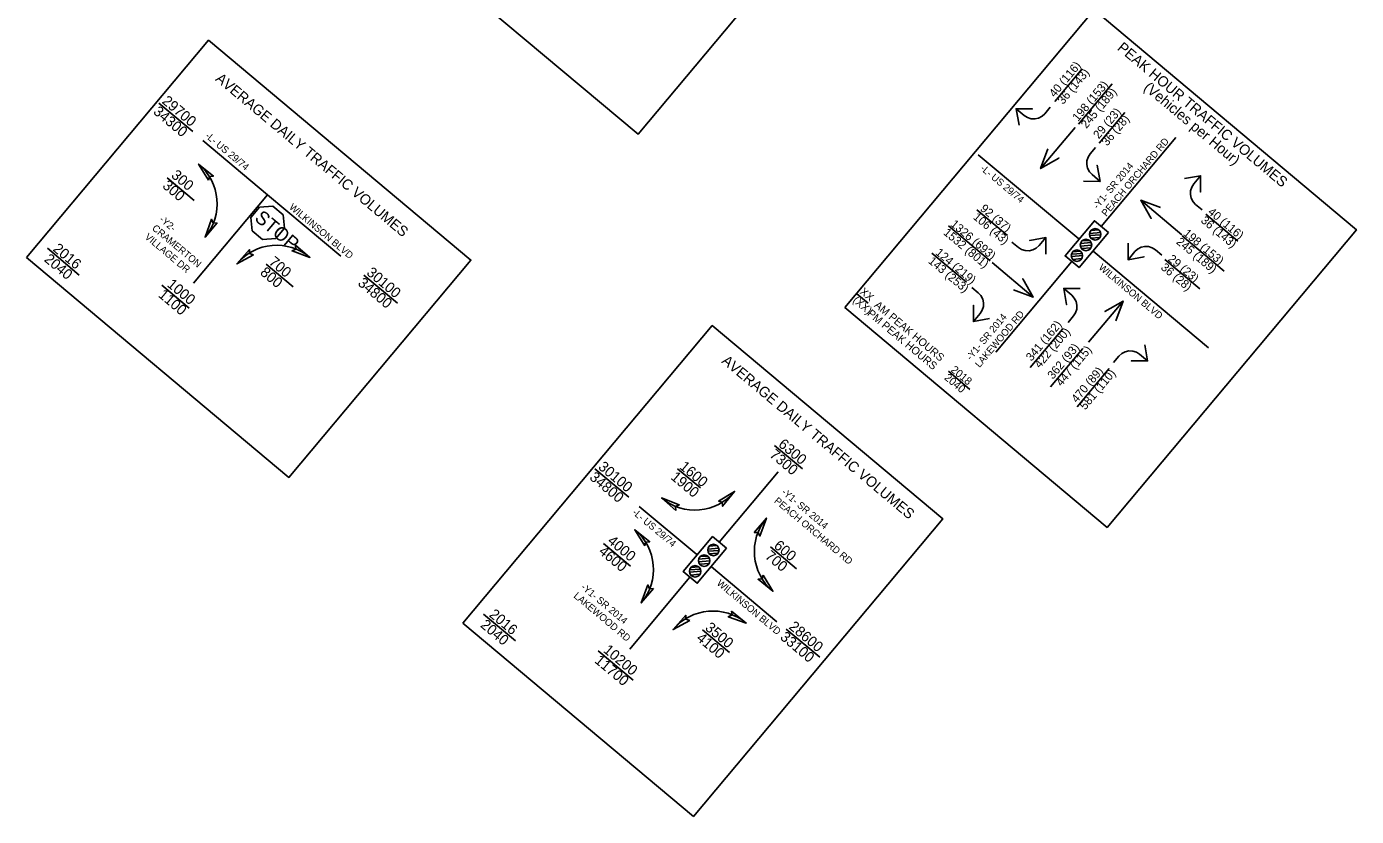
# Model space of a CAD drawing. Extents: x 1257249 to 1258387, y 800228 to 800957.
# Drawn here: x 1257747 to 1258387, y 800228 to 800608 of the extents above; entities that cross this region are included whole.
import ezdxf

# ---------------------------------------------------------------- set-up
doc = ezdxf.new("R2010")
doc.units = 0
for name, color, linetype in [('Exist PHM Traffic Signal CELL', 7, 'Continuous'), ('Pattern 1', 7, 'Continuous'), ('Prop DSN Text', 7, 'Continuous')]:
    doc.layers.add(name, color=color, linetype=linetype)

msp = doc.modelspace()

# ---------------------------------------------------------------- linework, layer by layer
at = {"layer": 'Exist PHM Traffic Signal CELL'}
for p, q in [((1258255.41, 800505.27), (1258258.81, 800505.44)), ((1258258.95, 800508.87), (1258264.32, 800509.34)), ((1258258.96, 800507.8), (1258264.42, 800508.2)), ((1258259.64, 800506.58), (1258263.87, 800506.95)), ((1258259.68, 800510.22), (1258263.41, 800510.59)), ((1258250.18, 800498.89), (1258255.43, 800499.22)), ((1258250.88, 800500.02), (1258254.67, 800500.35)), ((1258254.54, 800504.04), (1258259.7, 800504.45)), ((1258254.57, 800502.71), (1258259.94, 800503.19)), ((1258255.11, 800501.61), (1258259.66, 800501.88)), ((1258250.28, 800497.74), (1258255.65, 800498.22)), ((1258250.9, 800496.33), (1258255.07, 800496.75)), ((1258075.8, 800358.24), (1258079.53, 800358.61)), ((1258070.66, 800352.06), (1258075.82, 800352.47)), ((1258071.53, 800353.29), (1258074.93, 800353.46)), ((1258075.07, 800356.89), (1258080.44, 800357.36)), ((1258075.08, 800355.82), (1258080.54, 800356.22)), ((1258075.76, 800354.6), (1258079.99, 800354.97)), ((1258066.3, 800346.91), (1258071.55, 800347.24)), ((1258066.4, 800345.77), (1258071.77, 800346.24)), ((1258067, 800348.04), (1258070.79, 800348.37)), ((1258070.69, 800350.74), (1258076.06, 800351.21)), ((1258071.23, 800349.63), (1258075.78, 800349.9)), ((1258067.01, 800344.36), (1258071.19, 800344.77))]:
    msp.add_line(p, q, dxfattribs=at)
for points in [[(1258268.04, 800509.25), (1258261.28, 800514.91), (1258247.15, 800498.05), (1258253.9, 800492.39)], [(1258084.16, 800357.27), (1258077.4, 800362.93), (1258063.27, 800346.07), (1258070.02, 800340.41)]]:
    msp.add_lwpolyline(points, close=True, dxfattribs=at)
for centre in [(1258257.24, 800503.26), (1258261.68, 800508.41), (1258252.89, 800498.14), (1258077.8, 800356.43), (1258073.36, 800351.29), (1258069.01, 800346.17)]:
    msp.add_circle(centre, 2.74, dxfattribs=at)
at = {"layer": 'Pattern 1'}
for points in [[(1258240.03, 800569.57), (1258237.43, 800566.47), (1258236.07, 800565.22), (1258234.43, 800564.36), (1258232.62, 800563.96), (1258230.77, 800564.04), (1258229.01, 800564.59), (1258227.45, 800565.59), (1258223.57, 800568.84), (1258231.44, 800568.82), (1258223.57, 800568.84), (1258224.98, 800561.04)], [(1258251.98, 800559.81), (1258235.39, 800540.02), (1258244.16, 800545.08), (1258235.39, 800540.02), (1258238.85, 800549.53)], [(1258261.85, 800550.26), (1258259.25, 800547.16), (1258258.26, 800545.6), (1258257.7, 800543.83), (1258257.62, 800541.99), (1258258.02, 800540.18), (1258258.88, 800538.54), (1258260.13, 800537.17), (1258264.01, 800533.92), (1258262.61, 800541.67), (1258264.01, 800533.92), (1258256.08, 800533.95)], [(1258313.13, 800520.16), (1258310.03, 800522.76), (1258308.78, 800524.13), (1258307.92, 800525.77), (1258307.52, 800527.57), (1258307.6, 800529.42), (1258308.16, 800531.19), (1258309.15, 800532.75), (1258312.4, 800536.63), (1258312.38, 800528.76), (1258312.4, 800536.63), (1258304.6, 800535.22)], [(1258303.37, 800508.22), (1258283.58, 800524.81), (1258288.65, 800516.04), (1258283.58, 800524.81), (1258293.1, 800521.35)], [(1258221.59, 800504.7), (1258224.69, 800502.09), (1258226.25, 800501.1), (1258228.02, 800500.55), (1258229.87, 800500.47), (1258231.67, 800500.87), (1258233.31, 800501.72), (1258234.68, 800502.97), (1258237.93, 800506.85), (1258230.18, 800505.46), (1258237.93, 800506.85), (1258237.9, 800498.93)], [(1258221.59, 800504.7), (1258224.69, 800502.09), (1258226.25, 800501.1), (1258228.02, 800500.55), (1258229.87, 800500.47), (1258231.67, 800500.87), (1258233.31, 800501.72), (1258234.68, 800502.97), (1258237.93, 800506.85), (1258230.18, 800505.46), (1258237.93, 800506.85), (1258237.9, 800498.93)], [(1258293.83, 800498.35), (1258290.72, 800500.95), (1258289.16, 800501.94), (1258287.4, 800502.49), (1258285.55, 800502.57), (1258283.74, 800502.17), (1258282.1, 800501.32), (1258280.74, 800500.07), (1258277.49, 800496.19), (1258285.23, 800497.58), (1258277.49, 800496.19), (1258277.51, 800504.11)], [(1258212.05, 800494.82), (1258231.83, 800478.23), (1258226.77, 800487), (1258231.83, 800478.23), (1258222.32, 800481.69)], [(1258212.05, 800494.82), (1258231.83, 800478.23), (1258226.77, 800487), (1258231.83, 800478.23), (1258222.32, 800481.69)], [(1258202.28, 800482.88), (1258205.38, 800480.28), (1258206.64, 800478.91), (1258207.49, 800477.27), (1258207.89, 800475.47), (1258207.81, 800473.62), (1258207.26, 800471.85), (1258206.26, 800470.29), (1258203.01, 800466.41), (1258203.03, 800474.28), (1258203.01, 800466.41), (1258210.81, 800467.82)], [(1258202.28, 800482.88), (1258205.38, 800480.28), (1258206.64, 800478.91), (1258207.49, 800477.27), (1258207.89, 800475.47), (1258207.81, 800473.62), (1258207.26, 800471.85), (1258206.26, 800470.29), (1258203.01, 800466.41), (1258203.03, 800474.28), (1258203.01, 800466.41), (1258210.81, 800467.82)], [(1258248.65, 800466.01), (1258251.25, 800469.11), (1258252.24, 800470.67), (1258252.8, 800472.44), (1258252.88, 800474.29), (1258252.47, 800476.09), (1258251.62, 800477.73), (1258250.37, 800479.1), (1258246.49, 800482.35), (1258247.89, 800474.6), (1258246.49, 800482.35), (1258254.42, 800482.33)], [(1258258.52, 800456.47), (1258275.11, 800476.26), (1258266.34, 800471.19), (1258275.11, 800476.26), (1258271.65, 800466.74)], [(1258270.46, 800446.7), (1258273.07, 800449.8), (1258274.43, 800451.06), (1258276.07, 800451.91), (1258277.88, 800452.31), (1258279.72, 800452.23), (1258281.49, 800451.68), (1258283.05, 800450.68), (1258286.93, 800447.43), (1258279.06, 800447.45), (1258286.93, 800447.43), (1258285.52, 800455.23)]]:
    msp.add_lwpolyline(points, dxfattribs=at)
for points in [[(1257834.64, 800534.44), (1257829.91, 800542.24), (1257837.05, 800536.47), (1257835.09, 800536.28)], [(1257838.89, 800514.02), (1257833.01, 800507.03), (1257836.19, 800515.65), (1257836.99, 800513.85)], [(1257856.33, 800498.6), (1257848.34, 800494.18), (1257854.39, 800501.09), (1257854.5, 800499.12)], [(1257876.52, 800503.11), (1257883.56, 800497.28), (1257874.91, 800500.4), (1257876.71, 800501.21)], [(1258080.24, 800379.88), (1258088.05, 800384.61), (1258082.27, 800377.47), (1258082.09, 800379.43)], [(1258059.67, 800375.46), (1258052.83, 800381.51), (1258061.37, 800378.11), (1258059.55, 800377.36)], [(1258097.5, 800364.78), (1258103.38, 800371.77), (1258100.2, 800363.15), (1258099.4, 800364.94)], [(1258044.72, 800358.38), (1258039.98, 800366.18), (1258047.13, 800360.41), (1258045.17, 800360.22)], [(1258048.96, 800337.96), (1258043.09, 800330.96), (1258046.27, 800339.59), (1258047.07, 800337.79)], [(1258101.79, 800344.39), (1258106.48, 800336.55), (1258099.37, 800342.37), (1258101.33, 800342.54)], [(1258086.6, 800327.04), (1258093.63, 800321.22), (1258084.99, 800324.34), (1258086.78, 800325.15)], [(1258066.4, 800322.54), (1258058.41, 800318.12), (1258064.47, 800325.03), (1258064.58, 800323.06)]]:
    msp.add_lwpolyline(points, close=True, dxfattribs=at)
for centre, start, end in [((1257813.85, 800523.08), 320.03429, 50.03429), ((1257867.5, 800478.12), 50.03429, 140.03429), ((1258068.89, 800400.67), 230.03429, 320.03429), ((1258122.54, 800355.71), 140.03429, 230.03429), ((1258023.93, 800347.02), 320.03429, 50.03429), ((1258077.58, 800302.06), 50.03429, 140.03429)]:
    msp.add_arc(centre, 25, start, end, dxfattribs=at)
at = {"layer": 'Prop DSN Text'}
for p, q in [((1258255.41, 800588.14), (1258242.2, 800572.38)), ((1258269.86, 800580.88), (1258253.63, 800561.52)), ((1257810.69, 800571.63), (1257827.07, 800557.9)), ((1258275.96, 800567.06), (1258263.59, 800552.31)), ((1257832.03, 800553.52), (1257863.16, 800527.43)), ((1258300.47, 800555.08), (1258264.54, 800512.21)), ((1258205.38, 800546.7), (1258253.73, 800506.18)), ((1257814.8, 800535.6), (1257827.86, 800524.66)), ((1257863.16, 800527.43), (1257827.45, 800484.83)), ((1257863.16, 800527.43), (1257898.35, 800497.93)), ((1257855.14, 800516.5), (1257859.26, 800521.43)), ((1257859.26, 800521.43), (1257865.72, 800522.01)), ((1257865.72, 800522.01), (1257870.66, 800517.87)), ((1258204.66, 800520.19), (1258219.42, 800507.82)), ((1257855.67, 800510.06), (1257855.14, 800516.5)), ((1257870.66, 800517.87), (1257871.22, 800511.41)), ((1258190.97, 800512.44), (1258211.07, 800495.59)), ((1258314.93, 800518.07), (1258330.36, 800505.14)), ((1257860.63, 800505.9), (1257855.67, 800510.06)), ((1257867.08, 800506.47), (1257860.63, 800505.9)), ((1257871.22, 800511.41), (1257867.08, 800506.47)), ((1258303.56, 800507.68), (1258323.77, 800490.74)), ((1257757.08, 800501.68), (1257772.44, 800488.81)), ((1258183.02, 800499.33), (1258199.63, 800485.41)), ((1258260.74, 800500.31), (1258316.21, 800453.82)), ((1257862.41, 800494.01), (1257875.46, 800483.07)), ((1258250.24, 800495.14), (1258213.76, 800451.61)), ((1258295.14, 800496.33), (1258312.06, 800482.15)), ((1257909.53, 800488.8), (1257925.73, 800475.22)), ((1257812.26, 800483.95), (1257825.4, 800472.94)), ((1258146.92, 800479.73), (1258152.35, 800475.19)), ((1258245.9, 800462.74), (1258230.39, 800444.23)), ((1258255.67, 800453.52), (1258240.16, 800435.01)), ((1258190.96, 800442.5), (1258201.38, 800433.76)), ((1258268.47, 800443.78), (1258252.96, 800425.28)), ((1258107.31, 800406.82), (1258120.77, 800395.54)), ((1258020.76, 800395.57), (1258037.15, 800381.84)), ((1258060.47, 800395.57), (1258071.55, 800386.29)), ((1258109.02, 800394.07), (1258080.66, 800360.23)), ((1258042.1, 800377.45), (1258069.84, 800354.21)), ((1258024.88, 800359.54), (1258037.93, 800348.6)), ((1258105.34, 800357.88), (1258117.85, 800347.4)), ((1258076.86, 800348.33), (1258108.43, 800321.87)), ((1258066.36, 800343.16), (1258037.53, 800308.77)), ((1257967.16, 800325.62), (1257982.52, 800312.75)), ((1258072.49, 800317.95), (1258085.54, 800307.01)), ((1258112.9, 800318.36), (1258129.1, 800304.78)), ((1258022.34, 800307.89), (1258039.26, 800293.71))]:
    msp.add_line(p, q, dxfattribs=at)
for points in [[(1257922.96, 800655.97), (1258041.53, 800556.6), (1258148, 800683.65), (1258029.43, 800783.02)], [(1258141.05, 800473.19), (1258267.38, 800367.31), (1258387.45, 800510.58), (1258261.11, 800616.46)], [(1257747.09, 800497.28), (1257873.43, 800391.39), (1257961.07, 800495.97), (1257834.73, 800601.85)], [(1257957.16, 800321.22), (1258068.17, 800228.18), (1258188.24, 800371.45), (1258077.23, 800464.48)]]:
    msp.add_lwpolyline(points, close=True, dxfattribs=at)

# ---------------------------------------------------------------- texts
for s, height, rotation, p in [('PEAK HOUR TRAFFIC VOLUMES', 5, 320.03429, (1258271.97, 800597.56)), ('40 (116)', 4.05, 50.03429, (1258242.13, 800574.07)), ('AVERAGE DAILY TRAFFIC VOLUMES', 5, 320.03429, (1257837.71, 800582.71)), ('36 (143)', 4.05, 50.03429, (1258246.2, 800570.66)), ('198 (153)', 4.05, 50.03429, (1258253.37, 800562.47)), ('245 (189)', 4.05, 50.03429, (1258257.44, 800559.06)), ('(Vehicles per Hour)', 5, 320.03429, (1258284.64, 800578.38)), ('34300', 5, 320.03429, (1257807.72, 800566.85)), ('29700', 5, 320.03429, (1257811.93, 800571.88)), ('29 (23)', 4.05, 50.03429, (1258263.38, 800554.08)), ('36 (28)', 4.05, 50.03429, (1258267.44, 800550.67)), ('-L- US 29/74 ', 3.375, 320.03429, (1257832.81, 800555.34)), ('PEACH ORCHARD RD', 3.375, 50.03429, (1258266.99, 800516.77)), ('300', 5, 320.03429, (1257816.35, 800536.2)), ('-L- US 29/74 ', 3.375, 320.03429, (1258206.06, 800539.67)), ('-Y1- SR 2014', 3.375, 50.03429, (1258262.79, 800520.29)), ('300', 5, 320.03429, (1257812.14, 800531.18)), ('STOP', 6.593, 320.03429, (1257856.44, 800515.5)), ('WILKINSON BLVD', 3.375, 320.03429, (1257873.25, 800520.98)), ('106 (43)', 4.05, 320.03429, (1258202.54, 800516.18)), ('92 (37)', 4.05, 320.03429, (1258205.95, 800520.25)), ('40 (116)', 4.05, 320.03429, (1258315.64, 800518.6)), ('CRAMERTON', 3.375, 320.03429, (1257807.22, 800510.86)), ('-Y2-', 3.375, 320.03429, (1257810.74, 800515.07)), ('1326 (693)', 4.05, 320.03429, (1258191.66, 800512.74)), ('36 (143)', 4.05, 320.03429, (1258312.23, 800514.53)), ('VILLAGE DR', 3.375, 320.03429, (1257803.7, 800506.66)), ('1532 (801)', 4.05, 320.03429, (1258188.25, 800508.67)), ('245 (189)', 4.05, 320.03429, (1258300.37, 800504.24)), ('198 (153)', 4.05, 320.03429, (1258303.78, 800508.31)), ('2016', 5, 320.03429, (1257759.4, 800500.79)), ('124 (219)', 4.05, 320.03429, (1258184.39, 800499.03)), ('2040', 5, 320.03429, (1257755.19, 800495.77)), ('800', 5, 320.03429, (1257859.17, 800489.41)), ('700', 5, 320.03429, (1257863.38, 800494.43)), ('143 (253)', 4.05, 320.03429, (1258180.97, 800494.96)), ('WILKINSON BLVD', 3.375, 320.03429, (1258263.04, 800491.92)), ('36 (28)', 4.05, 320.03429, (1258292.96, 800491.9)), ('29 (23)', 4.05, 320.03429, (1258296.37, 800495.97)), ('1000', 5, 320.03429, (1257814.36, 800483.66)), ('34800', 5, 320.03429, (1257906.22, 800484.3)), ('30100', 5, 320.03429, (1257910.43, 800489.32)), ('1100', 5, 320.03429, (1257810.15, 800478.64)), ('XX', 3.75, 320.03429, (1258148.02, 800480.2)), ('(XX)', 3.75, 320.03429, (1258144.6, 800476.13)), ('AM PEAK HOURS', 3.75, 320.03429, (1258155.01, 800473.81)), ('PM PEAK HOURS', 3.75, 320.03429, (1258151.6, 800469.74)), ('-Y1- SR 2014', 3.375, 50.03429, (1258201.79, 800447.51)), ('LAKEWOOD RD', 3.375, 50.03429, (1258205.99, 800443.99)), ('341 (162)', 4.05, 50.03429, (1258230.96, 800447.04)), ('422 (200)', 4.05, 50.03429, (1258235.03, 800443.63)), ('362 (93)', 4.05, 50.03429, (1258241.34, 800438.34)), ('447 (115)', 4.05, 50.03429, (1258245.41, 800434.93)), ('AVERAGE DAILY TRAFFIC VOLUMES', 5, 320.03429, (1258081.47, 800446.85)), ('2018', 3.75, 320.03429, (1258191.83, 800442.66)), ('470 (89)', 4.05, 50.03429, (1258252.85, 800427.01)), ('581 (110)', 4.05, 50.03429, (1258256.92, 800423.6)), ('2040', 3.75, 320.03429, (1258188.68, 800438.89)), ('6300', 5, 320.03429, (1258108.71, 800406.69)), ('7300', 5, 320.03429, (1258104.5, 800401.67)), ('30100', 5, 320.03429, (1258022, 800395.82)), ('1600', 5, 320.03429, (1258061.12, 800395.93)), ('34800', 5, 320.03429, (1258017.79, 800390.79)), ('1900', 5, 320.03429, (1258056.91, 800390.91)), ('-Y1- SR 2014', 3.375, 320.03429, (1258110.33, 800383.8)), ('PEACH ORCHARD RD', 3.375, 320.03429, (1258106.8, 800379.59)), ('-L- US 29/74 ', 3.375, 320.03429, (1258038.49, 800374.02)), ('4000', 5, 320.03429, (1258026.43, 800360.14)), ('600', 5, 320.03429, (1258106.55, 800357.86)), ('4600', 5, 320.03429, (1258022.22, 800355.12)), ('700', 5, 320.03429, (1258102.34, 800352.84)), ('-Y1- SR 2014', 3.375, 320.03429, (1258013.75, 800338.06)), ('WILKINSON BLVD', 3.375, 320.03429, (1258079.16, 800339.94)), ('LAKEWOOD RD', 3.375, 320.03429, (1258010.22, 800333.85)), ('2016', 5, 320.03429, (1257969.48, 800324.73)), ('2040', 5, 320.03429, (1257965.26, 800319.71)), ('3500', 5, 320.03429, (1258073.46, 800318.37)), ('28600', 5, 320.03429, (1258113.8, 800318.88)), ('4100', 5, 320.03429, (1258069.25, 800313.35)), ('33100', 5, 320.03429, (1258109.59, 800313.86)), ('10200', 5, 320.03429, (1258024.44, 800307.6)), ('11700', 5, 320.03429, (1258020.23, 800302.58))]:
    msp.add_text(s, height=height, rotation=rotation, dxfattribs=at).set_placement(p)

doc.saveas('drawing.dxf')
